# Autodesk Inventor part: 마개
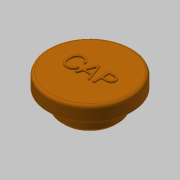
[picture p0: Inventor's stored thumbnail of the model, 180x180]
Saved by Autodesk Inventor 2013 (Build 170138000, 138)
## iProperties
Created: 2018-03
Part Number: 마개
Material: 고무
Document SubType Name: Modeling
Designer: mduedu
Density: 1 g/cm^3
Author: mduedu
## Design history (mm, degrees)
sketch "스케치1"
  geometry: C1 r 15 at (0, 0); 1 further point
  constraints: 1 centre point, 1 coincident
  dimensions: "d21" = 30 diameter of C1
extrude "돌출1" new body sketch "스케치1" distance "d2" = 6; taper "d3" = 0 deg
fillet "모깎기4" dims "d22" = 1
sketch "스케치6"
  geometry: C1 r 10 at (0, 0); 1 further point
  constraints: 1 centre point, 1 coincident
  dimensions: "d23" = 20 diameter of C1
extrude "돌출5" join sketch "스케치6" distance "d24" = 6; taper "d25" = 0 deg
sketch "스케치7"
  geometry: C1 r 7.5 at (0, 0); 1 further point
  constraints: 1 centre point, 1 coincident
  dimensions: "d26" = 15 diameter of C1
extrude "돌출6" cut sketch "스케치7" distance "d27" = 6; taper "d28" = 0 deg
sketch "스케치8"
  geometry: C1 r 15 at (0, 0) reference; C2 r 14 at (0, 0); 1 further point
  constraints: 1 centre point, 1 coincident
  dimensions: "d29" = 1 radial gap between concentric circles of C2 C1
extrude "돌출7" cut sketch "스케치8" distance "d30" = 1; taper "d31" = 0 deg
fillet "모깎기5" dims "d32" = 1
chamfer "모따기2" distance "d33" = 1; stored, may be unused: second distance "d34" = 2, angle "d35" = 45 deg
sketch "스케치5"
  geometry: 2 further points
  constraints: 1 coincident, 1 other
feature "엠보싱1" sketch "스케치5" dims "d19" = 0.5, "d20" = 0
node "솔리드1"
